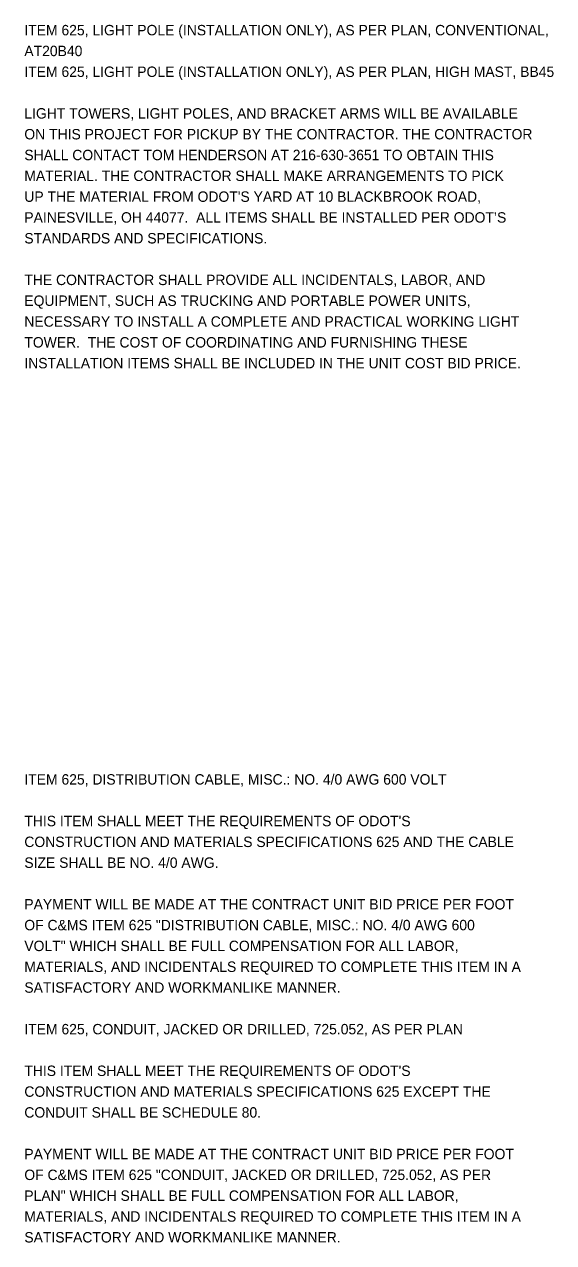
# Model space of a CAD drawing. Extents: x 0 to 49.8, y -1.8 to 22.
# Drawn here: x 42.65 to 49.76, y 4.76 to 21.15 of the extents above; entities that cross this region are included whole.
import ezdxf

# ---------------------------------------------------------------- set-up
doc = ezdxf.new("R2010")
doc.units = 0
doc.layers.add('SH_Text', color=7, linetype='Continuous')

msp = doc.modelspace()

# ---------------------------------------------------------------- texts
at = {"layer": 'SH_Text'}
for s, p in [('ITEM 625, LIGHT POLE (INSTALLATION ONLY), AS PER PLAN, CONVENTIONAL,', (42.645, 21)), ('AT20B40', (42.645, 20.72)), ('ITEM 625, LIGHT POLE (INSTALLATION ONLY), AS PER PLAN, HIGH MAST, BB45', (42.645, 20.44)), ('LIGHT TOWERS, LIGHT POLES, AND BRACKET ARMS WILL BE AVAILABLE ', (42.645, 19.88)), ('ON THIS PROJECT FOR PICKUP BY THE CONTRACTOR. THE CONTRACTOR ', (42.645, 19.6)), ('SHALL CONTACT TOM HENDERSON AT 216-630-3651 TO OBTAIN THIS ', (42.645, 19.32)), ('MATERIAL. THE CONTRACTOR SHALL MAKE ARRANGEMENTS TO PICK ', (42.645, 19.04)), ("UP THE MATERIAL FROM ODOT'S YARD AT 10 BLACKBROOK ROAD, ", (42.645, 18.76)), ('PAINESVILLE, OH 44077.  ALL ITEMS SHALL BE INSTALLED PER ODOT’S ', (42.645, 18.48)), ('STANDARDS AND SPECIFICATIONS.', (42.645, 18.2)), ('THE CONTRACTOR SHALL PROVIDE ALL INCIDENTALS, LABOR, AND ', (42.645, 17.64)), ('EQUIPMENT, SUCH AS TRUCKING AND PORTABLE POWER UNITS, ', (42.645, 17.36)), ('NECESSARY TO INSTALL A COMPLETE AND PRACTICAL WORKING LIGHT ', (42.645, 17.08)), ('TOWER.\xa0 THE COST OF COORDINATING AND FURNISHING THESE ', (42.645, 16.8)), ('INSTALLATION ITEMS SHALL BE INCLUDED IN THE UNIT COST BID PRICE.', (42.645, 16.52)), ('ITEM 625, DISTRIBUTION CABLE, MISC.: NO. 4/0 AWG 600 VOLT', (42.645, 10.92)), ("THIS ITEM SHALL MEET THE REQUIREMENTS OF ODOT'S ", (42.645, 10.36)), ('CONSTRUCTION AND MATERIALS SPECIFICATIONS 625 AND THE CABLE ', (42.645, 10.08)), ('SIZE SHALL BE NO. 4/0 AWG.', (42.645, 9.8)), ('PAYMENT WILL BE MADE AT THE CONTRACT UNIT BID PRICE PER FOOT ', (42.645, 9.24)), ('OF C&MS ITEM 625 "DISTRIBUTION CABLE, MISC.: NO. 4/0 AWG 600 ', (42.645, 8.96)), ('VOLT" WHICH SHALL BE FULL COMPENSATION FOR ALL LABOR, ', (42.645, 8.68)), ('MATERIALS, AND INCIDENTALS REQUIRED TO COMPLETE THIS ITEM IN A ', (42.645, 8.4)), ('SATISFACTORY AND WORKMANLIKE MANNER.', (42.645, 8.12)), ('ITEM 625, CONDUIT, JACKED OR DRILLED, 725.052, AS PER PLAN', (42.645, 7.56)), ("THIS ITEM SHALL MEET THE REQUIREMENTS OF ODOT'S ", (42.645, 7)), ('CONSTRUCTION AND MATERIALS SPECIFICATIONS 625 EXCEPT THE ', (42.645, 6.72)), ('CONDUIT SHALL BE SCHEDULE 80.', (42.645, 6.44)), ('PAYMENT WILL BE MADE AT THE CONTRACT UNIT BID PRICE PER FOOT ', (42.645, 5.88)), ('OF C&MS ITEM 625 "CONDUIT, JACKED OR DRILLED, 725.052, AS PER ', (42.645, 5.6)), ('PLAN" WHICH SHALL BE FULL COMPENSATION FOR ALL LABOR, ', (42.645, 5.32)), ('MATERIALS, AND INCIDENTALS REQUIRED TO COMPLETE THIS ITEM IN A ', (42.645, 5.04)), ('SATISFACTORY AND WORKMANLIKE MANNER.', (42.645, 4.76))]:
    msp.add_text(s, height=0.14, dxfattribs=at).set_placement(p)

doc.saveas('drawing.dxf')
